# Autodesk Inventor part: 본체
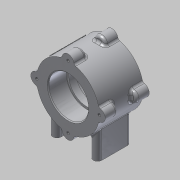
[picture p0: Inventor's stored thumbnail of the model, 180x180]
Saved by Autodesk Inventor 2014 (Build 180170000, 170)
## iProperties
Created: 2015-03
Part Number: 본체
Material: 알루미늄 6061
Document SubType Name: Modeling
Designer: MYHOME
Mass: 450.776 g
Surface Area: 332.745 cm^2
Volume: 166.338 cm^3
Density: 2.71 g/cm^3
Appearance: 알루미늄 - 평지
Author: MYHOME
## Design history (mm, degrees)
sketch "스케치2"
  geometry: C1 r 37 at (0, 0); 1 further point
  constraints: 1 centre point, 1 coincident
  dimensions: "d0" = 74 diameter of C1
extrude "돌출1" new body sketch "스케치2" stored distance "d1" = 52; taper "d2" = 0 deg
sketch "스케치3"
  geometry: C1 r 7 at (-37, 0); C2 r 7 at (0, 37); C3 r 7 at (37, 0); C4 r 7 at (0, -37); A1 r 37 centre (0, 0) between (-37, 0) and (0, 37) reference
  constraints: 4 centre point, 4 point on circle, 3 equal radius, 2 horizontal alignment, 2 vertical alignment
  dimensions: "d3" = 14 diameter of C1
extrude "돌출2" join sketch "스케치3" distance "d5" = 15; taper "d6" = 0 deg
sketch "스케치4"
  geometry: A1 r 7 centre (37, 0) between (36.338, -6.969) and (36.338, 6.969) reference; A2 r 7 centre (0, 37) between (6.969, 36.338) and (-6.969, 36.338) reference; A3 r 7 centre (-37, 0) between (-36.338, 6.969) and (-36.338, -6.969) reference; A4 r 7 centre (0, -37) between (-6.969, -36.338) and (6.969, -36.338) reference
hole "구멍1" sketch "스케치4" at (0, 37), (37, 0), (0, -37), (-37, 0) diameter "d7" = 3.242; stored, may be unused: countersink angle "d11" = 90 deg, drill point angle "d13" = 118 deg; dims "d8" = 8, "d9" = 4, "d10" = 2, "d12" = 11
sketch "스케치5"
  geometry: C1 r 23.5 at (0, 0); A1 r 37 centre (0, 0) between (-36.338, -6.969) and (-6.969, -36.338) reference
  constraints: 1 centre point, 1 coincident
  dimensions: "d14" = 47 diameter of C1
extrude "돌출3" cut sketch "스케치5" distance "d15" = 22; taper "d16" = 0 deg
node "작업 평면1"
sketch "스케치7"
  geometry: L1 (-24, -15)-(-24, 15); L2 (-29, -15)-(-29, 15); L3 (-19, 15)-(-19, -15); L4 (24, -15)-(24, 15); L5 (29, -15)-(29, 15); L6 (19, 15)-(19, -15); A1 r 5 centre (-24, -15) between (-29, -15) and (-19, -15); A2 r 5 centre (-24, 15) between (-19, 15) and (-29, 15); A3 r 5 centre (24, -15) between (19, -15) and (29, -15); A4 r 5 centre (24, 15) between (29, 15) and (19, 15); 3 further points
  constraints: 16 end point, 8 point on circle, 8 tangent, 4 centre point, 3 horizontal alignment, 3 parallel, 2 midpoint, 1 vertical
  dimensions: "d18" = 5 radius of A2; "d19" = 40 dimension on A1 A2; "d20" = 40 dimension on A3 A4; "d21" = 5 radius of A4; "d22" = 48 distance of point (24, 0) point (-24, 0); "d23" = 24 distance of point (0, 0) point (-24, 0)
extrude "돌출4" join sketch "스케치7" stored distance "d24" = 22; taper "d25" = 0 deg
fillet "모깎기1" dims "d26" = 3
chamfer "모따기1" distance "d27" = 1; stored, may be unused: second distance "d28" = 2, angle "d29" = 45 deg
chamfer "모따기2" distance "d30" = 1; stored, may be unused: second distance "d31" = 2, angle "d32" = 45 deg
fillet "모깎기2" dims "d33" = 3
fillet "모깎기3" dims "d34" = 3
sketch "스케치8"
  geometry: C1 r 23.5 at (0, 0) reference; C2 r 21 at (0, 0)
  constraints: 1 centre point, 1 coincident
  dimensions: "d35" = 42 diameter of C2
extrude "돌출5" cut sketch "스케치8" stored distance "d36" = 22; taper "d37" = 0 deg
fillet "모깎기4" dims "d38" = 0.3
sketch "스케치9"
  geometry: L1 (0, 0)-(37.062, 0); L2 (0, 0)-(26.163, 26.163); C1 r 21 at (0, 0) reference; A1 r 37 centre (0, 0) between (35.862, 9.104) and (9.104, 35.862) reference; 2 further points
  constraints: 4 end point, 2 point on circle, 1 horizontal
  dimensions: "d39" = 45 deg angle of L1 L2
node "작업 평면2"
sketch "스케치10"
  geometry: 2 further points
  constraints: 1 coincident, 1 other
feature "엠보싱1" sketch "스케치10" dims "d40" = 0.5, "d41" = 0
sketch "스케치11"
  geometry: L1 (-29, -15)-(-29, 15) reference; L2 (-19, 15)-(-19, -15) reference; A1 r 5 centre (24, 15) between (29, 15) and (19, 15) reference; A2 r 5 centre (24, -15) between (19, -15) and (29, -15) reference; A3 r 5 centre (-24, -15) between (-29, -15) and (-19, -15) reference; A4 r 5 centre (-24, 15) between (-19, 15) and (-29, 15) reference; 1 further point
hole "구멍2" sketch "스케치11" at (24, 15), (24, -15), (-24, -15), (-24, 15) diameter "d42" = 4.134; stored, may be unused: countersink angle "d46" = 90 deg, drill point angle "d48" = 118 deg; dims "d43" = 6, "d44" = 4, "d45" = 2, "d47" = 8
node "솔리드1"
mirror "대칭1"
node "투영된 루프1"
other parameters: "d17" = -56
